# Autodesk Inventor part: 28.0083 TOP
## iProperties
Created: 2006-12
Part Number: 28.0083 TOP
Document SubType Name: Modeling
Designer: Andy Moles
Material: Aluminum-6061
Density: 2.71 g/cm^3
Author: Andy Moles
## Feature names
1. Extrusion1
2. Extrusion2
3. Hole1
4. Hole2
5. Extrusion3
6. Chamfer1
